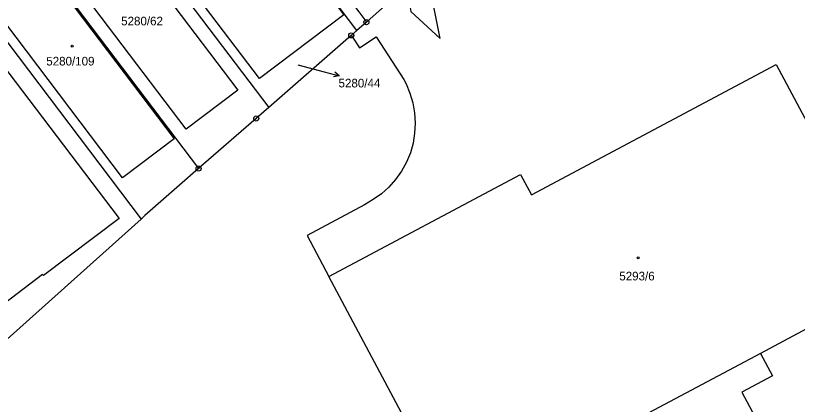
# Model space of a CAD drawing. Extents: x -644096 to -634268, y -1141430 to -1133463.
# Drawn here: x -637778.1 to -637624.4, y -1140149.4 to -1140072.9 of the extents above; entities that cross this region are included whole.
import ezdxf

# ---------------------------------------------------------------- set-up
doc = ezdxf.new("R2010")
doc.units = 0
for name, color, linetype in [('_CIVIL_CONSTRUCTION', 7, 'Continuous'), ('M_Svah_Zarez', 7, 'Continuous'), ('svrsek_osa_VRT', 7, 'Continuous'), ('svrsek_popisy_VRT', 7, 'Continuous'), ('terminal_VRT', 7, 'Continuous')]:
    doc.layers.add(name, color=color, linetype=linetype)

msp = doc.modelspace()

# ---------------------------------------------------------------- linework, layer by layer
at = {"layer": '_CIVIL_CONSTRUCTION'}
for centre, radius in [((-637709.14, -1140074.2), 0.5), ((-637709.14, -1140074.2), 0.0303), ((-637712.13, -1140076.81), 0.5), ((-637712.13, -1140076.81), 0.0303), ((-637730.8, -1140093.17), 0.5), ((-637730.8, -1140093.17), 0.0303), ((-637742.13, -1140103.04), 0.5), ((-637742.13, -1140103.04), 0.0303)]:
    msp.add_circle(centre, radius, dxfattribs=at)
at = {"layer": 'M_Svah_Zarez'}
for centre in [(-637766.99, -1140078.93), (-637655.71, -1140120.6)]:
    msp.add_circle(centre, 0.175, dxfattribs=at)
at = {"layer": 'svrsek_popisy_VRT'}
for p, q in [((-637722.63, -1140082.63), (-637717.42, -1140083.99)), ((-637717.42, -1140083.99), (-637714.52, -1140084.77)), ((-637714.52, -1140084.77), (-637715.36, -1140084.02)), ((-637714.52, -1140084.77), (-637715.62, -1140084.99))]:
    msp.add_line(p, q, dxfattribs=at)
at = {"layer": 'terminal_VRT'}
for p, q in [((-637783.61, -1140048.2), (-637742.13, -1140103.04)), ((-637795.32, -1140057.57), (-637753.43, -1140112.96)), ((-637711.01, -1140075.83), (-637724.13, -1140058.48)), ((-637709.14, -1140074.2), (-637711.01, -1140075.83)), ((-637711.01, -1140075.83), (-637712.13, -1140076.81)), ((-637712.13, -1140076.81), (-637728.34, -1140091.03)), ((-637753.43, -1140112.96), (-637787.68, -1140143.64)), ((-637600.43, -1140122.74), (-637631.69, -1140139.41)), ((-637691.52, -1140171.2), (-637716.54, -1140124.25))]:
    msp.add_line(p, q, dxfattribs=at)
for points in [[(-637755.35, -1140023.67), (-637749.35, -1140024.42), (-637744.64, -1140028.02), (-637744.26, -1140028.71), (-637744.09, -1140029.36), (-637744.26, -1140030.01), (-637744.77, -1140030.73), (-637741.17, -1140035.4), (-637739.81, -1140034.99), (-637738.41, -1140035.62), (-637731.25, -1140045.32), (-637724.55, -1140054.08), (-637724.09, -1140054.96), (-637723.86, -1140055.92), (-637723.81, -1140056.92), (-637724.07, -1140058.08), (-637720.43, -1140062.99), (-637719.53, -1140062.58), (-637718.55, -1140062.62), (-637717.68, -1140063.07), (-637717.32, -1140063.44), (-637710.62, -1140072.15), (-637709.44, -1140073.76), (-637709.14, -1140074.2)], [(-637764.95, -1140042.62), (-637759.67, -1140049.6), (-637751.15, -1140060.87), (-637750.67, -1140061.5), (-637728.34, -1140091.03)], [(-637702.26, -1140068.01), (-637700.61, -1140070.93), (-637700.39, -1140072.11), (-637694.64, -1140077.44), (-637696.09, -1140070.18), (-637695.9, -1140068.42), (-637693.88, -1140066.68), (-637668.35, -1140050.42), (-637660.75, -1140046.26), (-637656.5, -1140045.9), (-637649.2, -1140049.37), (-637644.85, -1140052.63), (-637624.17, -1140063.57)], [(-637744.59, -1140095.27), (-637773.88, -1140056.54), (-637763.73, -1140048.86), (-637734.44, -1140087.62), (-637744.59, -1140095.27)], [(-637786.36, -1140066.04), (-637776.22, -1140058.38), (-637746.95, -1140097.15), (-637757.1, -1140104.82), (-637786.36, -1140066.04)], [(-637724.13, -1140058.48), (-637724.25, -1140058.58), (-637713.56, -1140072.76), (-637730.14, -1140085.32), (-637742.03, -1140069.58), (-637741.17, -1140068.93)], [(-637787.63, -1140104.27), (-637805.51, -1140080.65), (-637809.37, -1140075.47), (-637794.58, -1140064.3), (-637757.76, -1140112.86), (-637772.62, -1140124.09), (-637772.8, -1140123.87), (-637790.31, -1140137.17), (-637805.14, -1140117.62), (-637787.63, -1140104.27)], [(-637702.26, -1140068.01), (-637707.79, -1140073.03), (-637709.14, -1140074.2)], [(-637712.13, -1140076.81), (-637711.87, -1140077.13), (-637710.5, -1140079.25), (-637707.25, -1140077.11), (-637701.81, -1140085.47), (-637701.36, -1140086.36), (-637700.59, -1140088.2), (-637700.02, -1140090.11), (-637699.69, -1140092.07), (-637699.57, -1140094.06), (-637699.66, -1140096.05), (-637699.98, -1140098.04), (-637700.5, -1140099.95), (-637701.29, -1140101.78), (-637702.25, -1140103.53), (-637703.4, -1140105.16), (-637704.71, -1140106.66), (-637706.18, -1140108), (-637707.82, -1140109.14), (-637709.53, -1140110.18), (-637720.81, -1140116.19), (-637716.54, -1140124.25)], [(-637716.54, -1140124.25), (-637678.87, -1140104.17), (-637676.67, -1140108.19), (-637628.58, -1140082.56), (-637615.88, -1140106.36), (-637610.67, -1140103.59), (-637600.43, -1140122.74)], [(-637728.34, -1140091.03), (-637730.8, -1140093.17), (-637742.13, -1140103.04)], [(-637742.13, -1140103.04), (-637745.9, -1140106.32), (-637752.69, -1140112.25), (-637753.43, -1140112.96)], [(-637631.69, -1140139.41), (-637629.32, -1140143.82), (-637635.37, -1140147.04), (-637627.76, -1140161.3), (-637627.48, -1140161.72), (-637627.08, -1140162.09), (-637626.64, -1140162.37), (-637626.17, -1140162.59), (-637625.64, -1140162.71), (-637625.13, -1140162.74), (-637624.68, -1140162.7), (-637624.09, -1140162.58), (-637594.05, -1140146.53), (-637593.21, -1140145.95), (-637592.5, -1140145.24), (-637591.92, -1140144.38), (-637591.47, -1140143.47), (-637591.15, -1140142.5), (-637591.06, -1140141.47), (-637591.08, -1140140.5), (-637591.81, -1140138.55), (-637600.28, -1140122.65), (-637600.43, -1140122.74)], [(-637631.69, -1140139.41), (-637691.47, -1140171.29), (-637691.52, -1140171.2)]]:
    msp.add_lwpolyline(points, dxfattribs=at)

# ---------------------------------------------------------------- texts
at = {"layer": 'svrsek_osa_VRT'}
for s, p in [('5280/62', (-637757.36, -1140074.83)), ('5280/109', (-637772.08, -1140082.73)), ('5280/44', (-637714.62, -1140087.05)), ('5293/6', (-637659.43, -1140125.04))]:
    msp.add_text(s, height=1.7, dxfattribs=at).set_placement(p)

doc.saveas('drawing.dxf')
